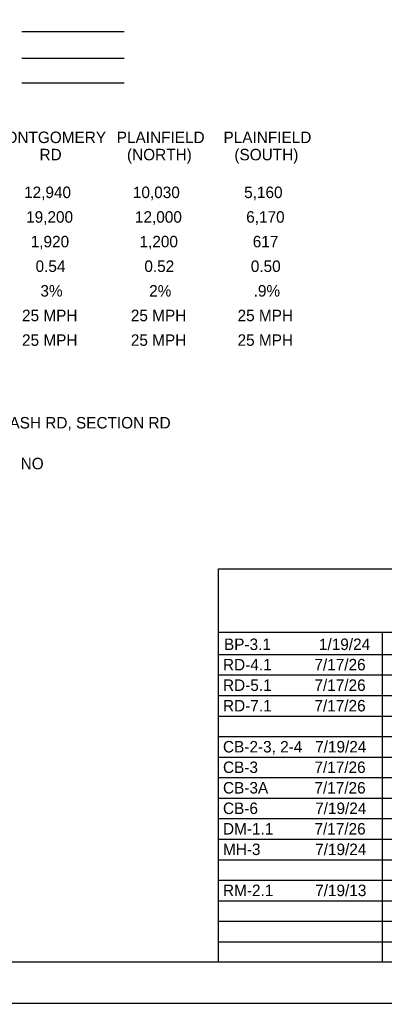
# Model space of a CAD drawing. Extents: x 0 to 34, y -3.9 to 26.2.
# Drawn here: x 7.72 to 12.17, y 0 to 11.98 of the extents above; entities that cross this region are included whole.
import ezdxf

# ---------------------------------------------------------------- set-up
doc = ezdxf.new("R2010")
doc.units = 0
for name, color, linetype in [('SH_Border', 7, 'Continuous'), ('SH_Cut_Line', 7, 'Continuous'), ('SH_Data', 7, 'Continuous'), ('SH_Text', 7, 'Continuous')]:
    doc.layers.add(name, color=color, linetype=linetype)

msp = doc.modelspace()

# ---------------------------------------------------------------- linework, layer by layer
at = {"layer": 'SH_Border'}
msp.add_lwpolyline([(1.5, 21.5), (33.5, 21.5), (33.5, 0.5), (1.5, 0.5)], close=True, dxfattribs=at)
at = {"layer": 'SH_Cut_Line'}
msp.add_lwpolyline([(0, 0), (34, 0), (34, 22), (0, 22)], close=True, dxfattribs=at)
at = {"layer": 'SH_Data'}
for p, q in [((9, 11.836), (7.75, 11.836)), ((9, 11.509), (7.75, 11.509)), ((9, 11.209), (7.75, 11.209)), ((10.15, 5.292), (23.6, 5.292)), ((10.15, 0.5), (10.15, 5.292)), ((10.15, 4.521), (23.6, 4.521)), ((12.15, 0.5), (12.15, 4.521)), ((10.15, 4.25), (23.6, 4.25)), ((10.15, 4), (23.6, 4)), ((10.15, 3.75), (23.6, 3.75)), ((10.15, 3.5), (23.6, 3.5)), ((10.15, 3.25), (23.6, 3.25)), ((10.15, 3), (23.6, 3)), ((10.15, 2.75), (23.6, 2.75)), ((10.15, 2.5), (23.6, 2.5)), ((10.15, 2.25), (23.6, 2.25)), ((10.15, 2), (23.6, 2)), ((10.15, 1.75), (23.6, 1.75)), ((10.15, 1.5), (23.6, 1.5)), ((10.15, 1.25), (23.6, 1.25)), ((10.15, 1), (23.6, 1)), ((10.15, 0.75), (23.6, 0.75))]:
    msp.add_line(p, q, dxfattribs=at)

# ---------------------------------------------------------------- texts
at = {"layer": 'SH_Text'}
for s, p in [('MONTGOMERY ', (7.396, 10.48)), ('PLAINFIELD', (8.909, 10.48)), ('PLAINFIELD', (10.211, 10.48)), ('RD', (7.967, 10.27)), ('(NORTH)', (9.034, 10.27)), ('(SOUTH)', (10.344, 10.27)), ('12,940 ', (7.779, 9.81)), ('10,030', (9.106, 9.81)), ('5,160', (10.463, 9.81)), ('19,200', (7.804, 9.51)), ('12,000', (9.131, 9.51)), ('6,170', (10.488, 9.51)), ('1,920', (7.86, 9.21)), ('1,200', (9.187, 9.21)), ('617', (10.568, 9.21)), ('0.54', (7.919, 8.91)), ('0.52', (9.246, 8.91)), ('0.50', (10.544, 8.91)), ('3%', (7.978, 8.61)), ('2%', (9.305, 8.61)), ('.9%', (10.579, 8.61)), ('25 MPH', (7.754, 8.31)), ('25 MPH', (9.081, 8.31)), ('25 MPH', (10.383, 8.31)), ('25 MPH', (7.754, 8.01)), ('25 MPH', (9.081, 8.01)), ('25 MPH', (10.383, 8.01)), ('COLLECTOR - PLAINFIELD (SOUTH OF MONTGOMERY), BLUE ASH RD, SECTION RD ', (1.994, 7.003)), ('NO', (7.737, 6.506)), ('BP-3.1', (10.217, 4.304)), ('1/19/24', (11.375, 4.304)), ('RD-4.1', (10.205, 4.056)), ('7/17/26', (11.32, 4.056)), ('RD-5.1', (10.205, 3.806)), ('7/17/26', (11.32, 3.806)), ('RD-7.1', (10.205, 3.556)), ('7/17/26', (11.32, 3.556)), ('CB-2-3, 2-4', (10.205, 3.056)), ('7/19/24', (11.329, 3.056)), ('CB-3', (10.205, 2.806)), ('7/17/26', (11.32, 2.806)), ('CB-3A', (10.205, 2.556)), ('7/17/26', (11.32, 2.556)), ('CB-6', (10.205, 2.306)), ('7/19/24', (11.329, 2.306)), ('DM-1.1', (10.205, 2.056)), ('7/17/26', (11.32, 2.056)), ('MH-3', (10.205, 1.806)), ('7/19/24', (11.329, 1.806)), ('RM-2.1', (10.205, 1.306)), ('7/19/13', (11.329, 1.306))]:
    msp.add_text(s, height=0.14, dxfattribs=at).set_placement(p)

doc.saveas('drawing.dxf')
